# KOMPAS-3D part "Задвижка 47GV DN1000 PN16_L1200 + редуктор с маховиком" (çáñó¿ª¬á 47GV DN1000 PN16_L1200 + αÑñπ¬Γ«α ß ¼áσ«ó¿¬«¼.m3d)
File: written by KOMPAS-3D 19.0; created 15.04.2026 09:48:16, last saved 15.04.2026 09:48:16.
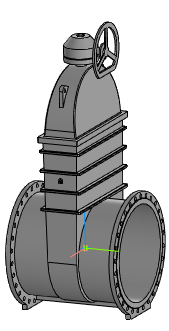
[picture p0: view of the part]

Document properties: Автор: Энергия; Полное имя файла: ..\..\Задвижка 47GV DN1000 PN16_L1200 + редуктор с маховиком.a3d

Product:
- Part/product: Задвижка 47GV DN1000 PN16_L1200 + редуктор с маховиком
    Масса: 5509.6

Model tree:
1. Операция без истории:1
